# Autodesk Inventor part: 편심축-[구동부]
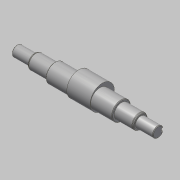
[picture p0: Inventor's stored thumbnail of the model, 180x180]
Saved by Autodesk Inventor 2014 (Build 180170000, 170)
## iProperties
Created: 2015-10
Part Number: 편심축-[구동부]
Document SubType Name: Modeling
Designer: mdu
Density: 7.86 g/cm^3
Material: 강철, 연강
Mass: 1267.06 g
Surface Area: 239.297 cm^2
Volume: 161.203 cm^3
Appearance: Steel
Author: mdu
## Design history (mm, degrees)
sketch "스케치1"
  geometry: L1 (-20.5, -41.331)-(-20.5, 32.669) reference; L2 (7.5, -30.031)-(7.5, 21.369) reference; L3 (135.5, -30.331)-(135.5, 21.669) reference; L4 (121.5, 21.369)-(121.5, -30.031) reference; L5 (184.5, -4.331)-(-57.5, -4.331); L6 (184.5, -4.331)-(184.5, 4.669); L7 (154.5, 8.169)-(121.5, 8.169); L8 (121.5, 8.169)-(121.5, 11.669); L9 (121.5, 11.669)-(7.5, 11.669); L10 (7.5, 11.669)-(7.5, 8.169); L11 (7.5, 8.169)-(-27.5, 8.169); L12 (-27.5, 8.169)-(-27.5, 4.669); L13 (-27.5, 4.669)-(-57.5, 4.669); L14 (-57.5, 4.669)-(-57.5, -4.331); L15 (154.5, 8.169)-(154.5, 4.669); L16 (154.5, 4.669)-(184.5, 4.669); C1 r 32.5 at (64.5, -4.331) reference; 1 further point
  constraints: 24 end point, 8 perpendicular, 5 point on line, 3 parallel, 2 collinear
  dimensions: "d1" = 25 diameter of L11 L5; "d2" = 32 diameter of L9 L5; "d3" = 18 diameter of L13 L5; "d4" = 35 distance of L10.end L11.end; "d5" = 30 distance of L12.end L13.end; "d15" = 33 distance of L7.start L7.end; "d26" = 30 distance of L15.end L6.end
revolve "회전1" sketch "스케치1" stored, may be unused: angle "d6" = 90 deg
node "작업 평면1"
sketch "스케치2"
  geometry: C1 r 16 at (0, 0) reference; C2 r 20.75 at (0, 4)
  constraints: 1 centre point, 1 vertical alignment
  dimensions: "d34" = 4 distance of C2.centre C1.centre; "d35" = 41.5 diameter of C2
extrude "돌출1" join sketch "스케치2" stored distance "d9" = 40; taper "d10" = 0 deg
chamfer "모따기1" distance "d11" = 1; stored, may be unused: second distance "d12" = 2, angle "d13" = 45 deg
node "작업 평면2"
sketch "스케치3"
  geometry: L1 (-15, -8)-(-15, 8) reference; L2 (-15, 3)-(0, 3); L3 (0, -3)-(-15, -3); A1 r 3 centre (0, 0) between (0, -3) and (0, 3); 2 further points
  constraints: 4 end point, 2 perpendicular, 2 point on circle, 2 point on line, 2 tangent, 1 centre point, 1 horizontal alignment, 1 midpoint
  dimensions: "d16" = 18 dimension on A1 L1; "d17" = 6 distance between parallel lines of L3 L2
extrude "돌출2" cut sketch "스케치3" distance "d18" = 3.5; taper "d19" = 0 deg
node "작업 평면3"
chamfer "모따기2" distance "d36" = 2.2; stored, may be unused: second distance "d37" = 2, angle "d38" = 30 deg
chamfer "모따기3" distance "d39" = 2.2; stored, may be unused: second distance "d40" = 2, angle "d41" = 30 deg
fillet "모깎기1" dims "d42" = 1, "d43" = 2
fillet "모깎기2" dims "d44" = 1, "d45" = 2
node "솔리드1"
mirror "대칭1"
node "참조1"
node "참조2"
node "참조3"
node "참조4"
node "참조5"
other parameters: "d30" = 35
